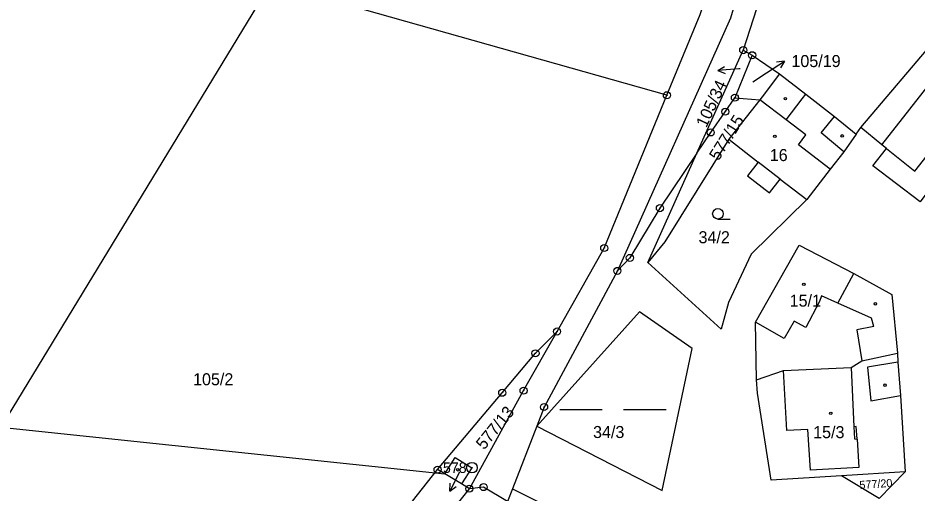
# Model space of a CAD drawing. Extents: x -758582 to -751794, y -998770 to -994350.
# Drawn here: x -754761.3 to -754634.2, y -996827.4 to -996760.3 of the extents above; entities that cross this region are included whole.
import ezdxf

# ---------------------------------------------------------------- set-up
doc = ezdxf.new("R2010")
doc.units = 0
for name, color, linetype in [('Hranice parcel', 7, 'Continuous'), ('Parcelní čísla', 7, 'Continuous'), ('Pop  PČ popisy', 7, 'Continuous'), ('Poz předměty', 7, 'Continuous'), ('Vnitřní kresba', 7, 'Continuous'), ('Značky bodu BP', 7, 'Continuous'), ('Značky budov', 7, 'Continuous'), ('Značky kultur', 7, 'Continuous')]:
    doc.layers.add(name, color=color, linetype=linetype)

msp = doc.modelspace()

# ---------------------------------------------------------------- linework, layer by layer
at = {"layer": 'Hranice parcel'}
for p, q in [((-754725.45, -996755.18), (-754788.01, -996857.97)), ((-754669.54, -996771.18), (-754716.28, -996757.97)), ((-754656.4, -996757.46), (-754658.75, -996764.81)), ((-754642.14, -996775.76), (-754630.49, -996762.03)), ((-754665.31, -996779.36), (-754658.75, -996764.81)), ((-754657.49, -996765.53), (-754659.93, -996771.53)), ((-754658.75, -996764.81), (-754657.49, -996765.53)), ((-754657.49, -996765.53), (-754653.62, -996768.16)), ((-754656.42, -996771.84), (-754660.78, -996777.41)), ((-754659.93, -996771.53), (-754656.42, -996771.84)), ((-754642.79, -996776.69), (-754642.14, -996775.76)), ((-754672.25, -996794.84), (-754665.31, -996779.36)), ((-754676.54, -996796.02), (-754686.9, -996815.27)), ((-754698.58, -996826.14), (-754700.95, -996824.72)), ((-754644.88, -996825), (-754654.82, -996825.63)), ((-754635.88, -996824.42), (-754644.88, -996825)), ((-754697.46, -996826.81), (-754698.58, -996826.14)), ((-754691.37, -996826.81), (-754692.08, -996828.64)), ((-754691.37, -996826.81), (-754681.61, -996831.68))]:
    msp.add_line(p, q, dxfattribs=at)
for points in [[(-754619.68, -996660.1), (-754626.86, -996659.32), (-754637.77, -996686.84), (-754649.79, -996724.29), (-754660.56, -996760.31), (-754676.54, -996796.02)], [(-754669.54, -996771.18), (-754664.86, -996759.76), (-754663.15, -996754.49)], [(-754653.62, -996768.16), (-754656.1, -996771.43), (-754656.42, -996771.84)], [(-754653.62, -996768.16), (-754649.92, -996771.03), (-754645.85, -996774.18), (-754642.79, -996776.69)], [(-754621.09, -996769.34), (-754633.76, -996786.26), (-754640.43, -996781.18), (-754638.51, -996778.73)], [(-754638.51, -996778.73), (-754634.52, -996781.92), (-754629.25, -996775.27), (-754628.08, -996776.26), (-754624.09, -996771.15), (-754622.2, -996768.72), (-754621.09, -996769.34)], [(-754685.07, -996804.59), (-754678.4, -996792.79), (-754669.54, -996771.18)], [(-754665.31, -996779.36), (-754663.35, -996776.44), (-754661.29, -996773.51), (-754659.93, -996771.53)], [(-754638.51, -996778.73), (-754639.16, -996778.21), (-754642.14, -996775.76)], [(-754642.79, -996776.69), (-754644.51, -996779.18), (-754646.48, -996781.64), (-754649.76, -996785.91)], [(-754660.78, -996777.41), (-754669.84, -996791.92), (-754672.25, -996794.84)], [(-754660.78, -996777.41), (-754656.66, -996780.66), (-754658.16, -996782.56), (-754655.03, -996784.97), (-754653.54, -996783.07), (-754649.76, -996785.91)], [(-754665.31, -996779.36), (-754670.53, -996787.15), (-754674.78, -996794.18), (-754676.54, -996796.02)], [(-754649.76, -996785.91), (-754657.62, -996793.64), (-754660.84, -996800.47), (-754661.88, -996804.24), (-754672.25, -996794.84)], [(-754656.87, -996811.4), (-754657.03, -996803.29), (-754650.86, -996792.39), (-754643.13, -996796.39), (-754637.75, -996799.35), (-754636.97, -996807.64)], [(-754665.98, -996806.97), (-754673.4, -996801.83), (-754687.94, -996817.96), (-754670.22, -996827.08), (-754665.98, -996806.97)], [(-754700.95, -996824.72), (-754701.96, -996824.12), (-754692.82, -996813.25), (-754688.12, -996807.67), (-754685.07, -996804.59)], [(-754697.46, -996826.81), (-754689.8, -996812.95), (-754685.07, -996804.59)], [(-754656.87, -996811.4), (-754653.04, -996810.12), (-754643.51, -996809.66), (-754641.97, -996808.73), (-754636.97, -996807.64)], [(-754636.97, -996807.64), (-754636.92, -996808.92), (-754636.5, -996813.63), (-754635.88, -996824.42)], [(-754654.82, -996825.63), (-754656.72, -996813.33), (-754656.87, -996811.4)], [(-754686.9, -996815.27), (-754687.94, -996817.96), (-754691.37, -996826.81)], [(-754700.95, -996824.72), (-754699.46, -996822.4), (-754697.1, -996823.84), (-754698.58, -996826.14)], [(-754635.88, -996824.42), (-754639.54, -996828.2), (-754644.88, -996825)], [(-754788.01, -996857.97), (-754777.86, -996859.14), (-754753.65, -996862.43), (-754736.1, -996862.72), (-754724.6, -996858.08), (-754709.52, -996842.19), (-754700.41, -996830.56), (-754697.46, -996826.81)], [(-754692.08, -996828.64), (-754695.46, -996826.59), (-754697.46, -996826.81)]]:
    msp.add_lwpolyline(points, dxfattribs=at)
at = {"layer": 'Pop  PČ popisy'}
for p, q in [((-754662.36, -996767.68), (-754661.4, -996767.11)), ((-754655.45, -996768), (-754652.93, -996766.37)), ((-754652.93, -996766.37), (-754654.05, -996766.49)), ((-754652.93, -996766.37), (-754653.5, -996767.33)), ((-754659.37, -996767.47), (-754662.36, -996767.68)), ((-754662.36, -996767.68), (-754661.33, -996768.11)), ((-754659.17, -996767.46), (-754659.37, -996767.47)), ((-754657.39, -996769.27), (-754655.45, -996768)), ((-754698.85, -996824.48), (-754700.21, -996827.15)), ((-754700.21, -996827.15), (-754700.2, -996826.03)), ((-754700.21, -996827.15), (-754699.31, -996826.49))]:
    msp.add_line(p, q, dxfattribs=at)
at = {"layer": 'Poz předměty'}
msp.add_line((-754780.86, -996816.32), (-754700.95, -996824.72), dxfattribs=at)
at = {"layer": 'Vnitřní kresba'}
for p, q in [((-754639.16, -996778.21), (-754631.17, -996767.99)), ((-754652.68, -996774.68), (-754656.42, -996771.84)), ((-754652.68, -996774.68), (-754650.41, -996771.68)), ((-754650.41, -996771.68), (-754649.92, -996771.03)), ((-754649.9, -996776.79), (-754652.68, -996774.68)), ((-754647.73, -996776.48), (-754645.85, -996774.18)), ((-754650.92, -996778.19), (-754649.9, -996776.79)), ((-754644.51, -996779.18), (-754647.73, -996776.48)), ((-754646.48, -996781.64), (-754650.92, -996778.19)), ((-754653.54, -996783.07), (-754656.66, -996780.66)), ((-754645.4, -996800.56), (-754643.13, -996796.39)), ((-754647.69, -996799.53), (-754647.99, -996800.35)), ((-754645.4, -996800.56), (-754647.69, -996799.53)), ((-754647.99, -996800.35), (-754649.9, -996804.01)), ((-754640.62, -996802.7), (-754645.4, -996800.56)), ((-754640.29, -996803.89), (-754640.62, -996802.7)), ((-754652.96, -996805.56), (-754657.03, -996803.29)), ((-754651.57, -996803.12), (-754652.96, -996805.56)), ((-754649.9, -996804.01), (-754651.57, -996803.12)), ((-754640.29, -996803.89), (-754642.69, -996804.37)), ((-754642.69, -996804.37), (-754641.97, -996808.73)), ((-754636.92, -996808.92), (-754641.19, -996809.65)), ((-754652.6, -996818.59), (-754653.04, -996810.12)), ((-754643.51, -996809.66), (-754643.12, -996818.06)), ((-754641.19, -996809.65), (-754640.7, -996814.39)), ((-754640.7, -996814.39), (-754636.5, -996813.63)), ((-754642.77, -996818.01), (-754643.12, -996818.06)), ((-754642.67, -996819.79), (-754642.77, -996818.01)), ((-754649.62, -996818.43), (-754652.6, -996818.59)), ((-754649.25, -996824.2), (-754649.62, -996818.43)), ((-754643.12, -996818.06), (-754643.04, -996819.78)), ((-754643.04, -996819.78), (-754642.67, -996819.79)), ((-754642.67, -996819.79), (-754642.42, -996823.82)), ((-754716.8, -996842.7), (-754701.96, -996824.12)), ((-754642.42, -996823.82), (-754649.25, -996824.2))]:
    msp.add_line(p, q, dxfattribs=at)
at = {"layer": 'Značky bodu BP'}
for centre, radius in [((-754658.75, -996764.81), 0.5), ((-754658.75, -996764.81), 0.0303), ((-754657.49, -996765.53), 0.5), ((-754657.49, -996765.53), 0.0303), ((-754669.54, -996771.18), 0.5), ((-754669.54, -996771.18), 0.0303), ((-754659.93, -996771.53), 0.5), ((-754659.93, -996771.53), 0.0303), ((-754661.29, -996773.51), 0.5), ((-754661.29, -996773.51), 0.0303), ((-754663.35, -996776.44), 0.5), ((-754663.35, -996776.44), 0.0303), ((-754670.53, -996787.15), 0.5), ((-754670.53, -996787.15), 0.0303), ((-754678.4, -996792.79), 0.5), ((-754678.4, -996792.79), 0.0303), ((-754674.78, -996794.18), 0.5), ((-754674.78, -996794.18), 0.0303), ((-754676.54, -996796.02), 0.5), ((-754676.54, -996796.02), 0.0303), ((-754685.07, -996804.59), 0.5), ((-754685.07, -996804.59), 0.0303), ((-754688.12, -996807.67), 0.5), ((-754688.12, -996807.67), 0.0303), ((-754692.82, -996813.25), 0.5), ((-754689.8, -996812.95), 0.5), ((-754689.8, -996812.95), 0.0303), ((-754692.82, -996813.25), 0.0303), ((-754686.9, -996815.27), 0.5), ((-754686.9, -996815.27), 0.0303), ((-754697.1, -996823.84), 0.75), ((-754701.96, -996824.12), 0.5), ((-754701.96, -996824.12), 0.0303), ((-754697.1, -996823.84), 0.03), ((-754697.46, -996826.81), 0.5), ((-754697.46, -996826.81), 0.0303), ((-754695.46, -996826.59), 0.5), ((-754695.46, -996826.59), 0.0303)]:
    msp.add_circle(centre, radius, dxfattribs=at)
at = {"layer": 'Značky budov'}
for centre in [(-754652.79, -996771.66), (-754654.29, -996777), (-754644.77, -996776.93), (-754650.19, -996797.92), (-754640.07, -996800.68), (-754638.71, -996812.17), (-754646.38, -996816.17), (-754699.11, -996824.14)]:
    msp.add_circle(centre, 0.175, dxfattribs=at)
at = {"layer": 'Značky kultur'}
for p, q in [((-754662.33, -996788.69), (-754660.58, -996788.69)), ((-754684.67, -996815.63), (-754678.67, -996815.63)), ((-754675.67, -996815.63), (-754669.67, -996815.63))]:
    msp.add_line(p, q, dxfattribs=at)
msp.add_circle((-754662.33, -996787.94), 0.75, dxfattribs=at)

# ---------------------------------------------------------------- texts
at = {"layer": 'Parcelní čísla'}
for s, p in [('105/19', (-754651.94, -996767.2)), ('16', (-754655, -996780.49)), ('34/2', (-754665.07, -996792.11)), ('15/1', (-754652.19, -996801.07)), ('105/2', (-754736.52, -996812.19)), ('34/3', (-754679.98, -996819.65)), ('15/3', (-754648.87, -996819.67))]:
    msp.add_text(s, height=1.7, dxfattribs=at).set_placement(p)
for s, height, rotation, p in [('105/34', 1.7, 65, (-754663.97, -996775.87)), ('577/15', 1.7, 58, (-754662.25, -996780.56)), ('577/13', 1.7, 51, (-754695.38, -996821.42)), ('577/20', 1.14, 4, (-754642.29, -996826.87))]:
    msp.add_text(s, height=height, rotation=rotation, dxfattribs=at).set_placement(p)
at = {"layer": 'Značky bodu BP'}
msp.add_text('578', height=1.5, dxfattribs=at).set_placement((-754701.2, -996824.59))

doc.saveas('drawing.dxf')
